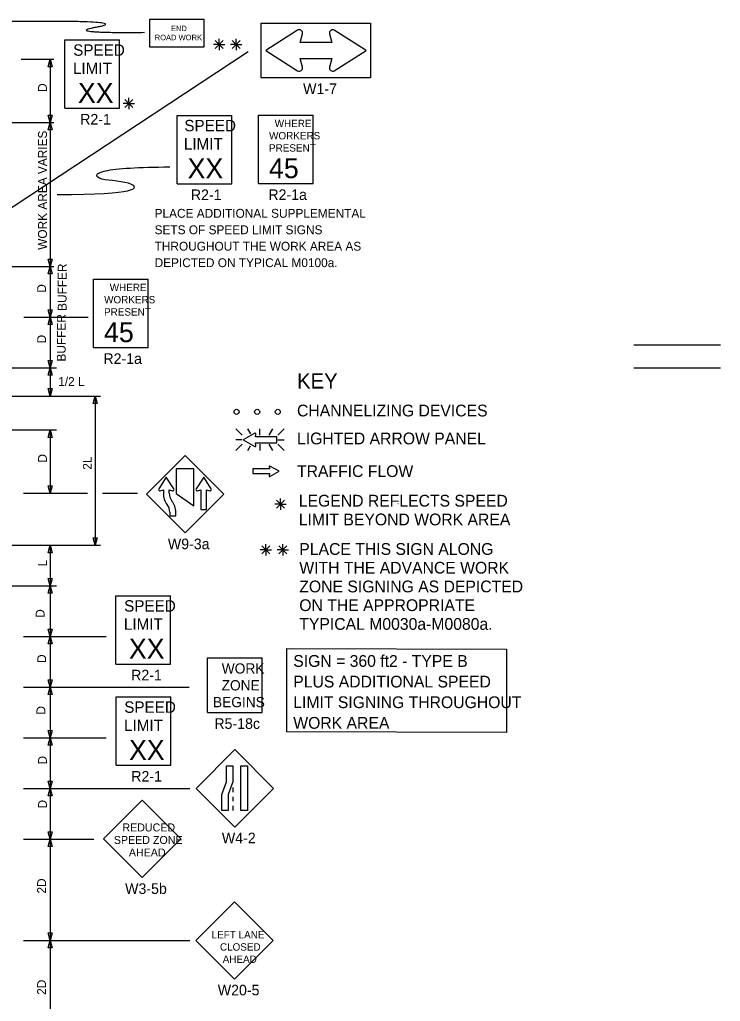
# Model space of a CAD drawing. Extents: x 16730 to 18482, y 5650 to 6977.
# Drawn here: x 17028 to 17582, y 6143 to 6919 of the extents above; entities that cross this region are included whole.
import ezdxf

# ---------------------------------------------------------------- set-up
doc = ezdxf.new("R2010")
doc.units = 0
for name, color, linetype in [('MT_SCRATCH_LEVEL_E', 7, 'Continuous'), ('TRAFFIC_SIGNS_PR', 7, 'Continuous'), ('TYPICAL_TEXT_DIMEN_EX', 7, 'Continuous'), ('TYPICAL_TEXT_DIMEN_PR', 7, 'Continuous')]:
    doc.layers.add(name, color=color, linetype=linetype)

msp = doc.modelspace()

# ---------------------------------------------------------------- linework, layer by layer
at = {"layer": 'MT_SCRATCH_LEVEL_E'}
for p, q in [((17225.23, 6563.7), (17211.98, 6563.7)), ((17211.98, 6563.7), (17211.98, 6559.96)), ((17224.92, 6565.48), (17225.23, 6563.7)), ((17232.84, 6561.85), (17225.6, 6565.96)), ((17225.6, 6557.7), (17232.84, 6561.85)), ((17211.98, 6559.96), (17225.23, 6559.96)), ((17225.23, 6559.96), (17224.92, 6558.18))]:
    msp.add_line(p, q, dxfattribs=at)
for centre, start, end in [((17225.38, 6565.55), 60.42484, 189.96381), ((17225.38, 6558.11), 170.03619, 299.77312)]:
    msp.add_arc(centre, 0.463, start, end, dxfattribs=at)
at = {"layer": 'TRAFFIC_SIGNS_PR'}
for p, q in [((17063.61, 6902.55), (17106.81, 6902.55)), ((17063.61, 6848.55), (17063.61, 6902.55)), ((17106.81, 6848.55), (17106.81, 6902.55)), ((17063.61, 6848.55), (17106.81, 6848.55)), ((17152.3, 6842.88), (17195.5, 6842.88)), ((17152.3, 6788.88), (17152.3, 6842.88)), ((17195.5, 6788.88), (17195.5, 6842.88)), ((17216.65, 6842.98), (17259.85, 6842.98)), ((17216.65, 6788.98), (17216.65, 6842.98)), ((17259.85, 6788.98), (17259.85, 6842.98)), ((17152.3, 6788.88), (17195.5, 6788.88)), ((17216.65, 6788.98), (17259.85, 6788.98)), ((17086.26, 6713.46), (17129.46, 6713.46)), ((17086.26, 6659.46), (17086.26, 6713.46)), ((17129.46, 6659.46), (17129.46, 6713.46)), ((17086.26, 6659.46), (17129.46, 6659.46)), ((17198.66, 6595.23), (17203.59, 6590.3)), ((17210.42, 6591.41), (17208.21, 6595.23)), ((17217.74, 6590.3), (17217.74, 6595.23)), ((17224.97, 6590.3), (17227.82, 6595.23)), ((17231.89, 6590.3), (17236.82, 6595.23)), ((17203.59, 6586.74), (17198.66, 6586.74)), ((17231.89, 6586.74), (17236.82, 6586.74)), ((17198.66, 6578.25), (17203.59, 6583.19)), ((17208.17, 6578.25), (17210.28, 6581.91)), ((17217.74, 6583.19), (17217.74, 6578.25)), ((17227.87, 6578.25), (17225.02, 6583.19)), ((17231.89, 6583.19), (17236.82, 6578.25)), ((17158.5, 6574.22), (17127.95, 6543.68)), ((17189.05, 6543.68), (17158.5, 6574.22)), ((17127.95, 6543.68), (17158.5, 6513.13)), ((17158.5, 6513.13), (17189.05, 6543.68)), ((17103.88, 6463.52), (17147.08, 6463.52)), ((17103.88, 6409.52), (17103.88, 6463.52)), ((17147.08, 6409.52), (17147.08, 6463.52)), ((17176.27, 6371.21), (17176.27, 6414.41)), ((17176.27, 6414.41), (17219.47, 6414.41)), ((17219.47, 6371.21), (17219.47, 6414.41)), ((17103.88, 6409.52), (17147.08, 6409.52)), ((17103.98, 6383.56), (17147.18, 6383.56)), ((17103.98, 6329.56), (17103.98, 6383.56)), ((17147.18, 6329.56), (17147.18, 6383.56)), ((17176.27, 6371.21), (17219.47, 6371.21)), ((17197.78, 6341.93), (17167.23, 6311.38)), ((17228.33, 6311.38), (17197.78, 6341.93)), ((17103.98, 6329.56), (17147.18, 6329.56)), ((17196.38, 6311.93), (17196.38, 6308.33)), ((17167.23, 6311.38), (17197.78, 6280.83)), ((17196.38, 6304.73), (17196.38, 6301.13)), ((17197.78, 6280.83), (17228.33, 6311.38)), ((17124.69, 6301.94), (17094.14, 6271.39)), ((17155.23, 6271.39), (17124.69, 6301.94)), ((17196.38, 6297.53), (17196.38, 6293.93)), ((17094.14, 6271.39), (17124.69, 6240.84)), ((17124.69, 6240.84), (17155.23, 6271.39)), ((17197.68, 6221.83), (17167.13, 6191.28)), ((17228.22, 6191.28), (17197.68, 6221.83)), ((17167.13, 6191.28), (17197.68, 6160.73)), ((17197.68, 6160.73), (17228.22, 6191.28))]:
    msp.add_line(p, q, dxfattribs=at)
for points in [[(17130.49, 6896.94), (17173.69, 6896.94), (17173.69, 6918.54), (17130.49, 6918.54)], [(17305.2, 6872.6), (17218.8, 6872.6), (17218.8, 6915.8), (17305.2, 6915.8)], [(17151.4, 6563.85), (17151.4, 6544.33), (17165.36, 6534.64), (17165.36, 6563.85)], [(17196.38, 6329.08), (17196.38, 6316.5), (17192.62, 6306.51), (17192.62, 6293.93), (17187.56, 6293.93), (17187.56, 6306.51), (17191.32, 6316.5), (17191.32, 6329.08)], [(17207.78, 6329.08), (17207.78, 6293.93), (17202.73, 6293.93), (17202.73, 6329.08)]]:
    msp.add_lwpolyline(points, close=True, dxfattribs=at)
for points in [[(17247.51, 6910.18), (17222.4, 6894.2), (17247.51, 6878.22)], [(17276.49, 6878.22), (17301.6, 6894.2), (17276.49, 6910.18)], [(17272.71, 6907.39), (17274.6, 6900.5), (17249.41, 6900.5), (17251.29, 6907.39)], [(17251.29, 6881.01), (17249.41, 6887.9), (17274.6, 6887.9), (17272.71, 6881.01)], [(17213.67, 6592.02), (17204.37, 6586.74), (17213.67, 6581.42)], [(17214.54, 6582.05), (17214.14, 6584.32), (17231.15, 6584.32), (17231.15, 6589.12), (17214.14, 6589.12), (17214.54, 6591.4)], [(17149.72, 6547.84), (17143.72, 6557.26), (17137.73, 6547.84)], [(17179.22, 6547.84), (17173.23, 6557.26), (17167.24, 6547.84)], [(17138.78, 6546.42), (17141.36, 6547.13), (17141.36, 6544.62)], [(17146.08, 6544.51), (17146.08, 6547.13), (17148.67, 6546.42)], [(17168.29, 6546.42), (17170.87, 6547.13), (17170.87, 6531.61), (17175.59, 6531.61), (17175.59, 6547.13), (17178.18, 6546.42)], [(17146.5, 6529.49), (17146.49, 6526.51), (17151.22, 6526.51), (17151.22, 6529.49)]]:
    msp.add_lwpolyline(points, dxfattribs=at)
for centre in [(17199.22, 6608.78), (17215.52, 6608.78), (17231.82, 6608.78)]:
    msp.add_circle(centre, 2, dxfattribs=at)
for centre, radius, start, end in [((17248.86, 6908.05), 2.52, 344.67308, 122.46963), ((17275.14, 6908.05), 2.52, 57.53038, 195.32692), ((17248.86, 6880.35), 2.52, 237.53038, 15.32692), ((17275.14, 6880.35), 2.52, 164.69282, 302.45235), ((17213.95, 6591.5), 0.598, 350.73078, 118.89165), ((17213.95, 6581.95), 0.597, 241.48329, 9.95933), ((17138.53, 6547.33), 0.945, 147.52044, 285.3986), ((17155.52, 6544.21), 14.17, 178.32933, 218.54273), ((17155.52, 6544.21), 9.45, 178.19356, 218.54646), ((17134.27, 6544.88), 11.81, 358.18937, 0.00483), ((17148.92, 6547.34), 0.947, 254.68281, 32.2708), ((17145.55, 6535.03), 11.81, 74.67996, 74.68078), ((17159.68, 6554.18), 11.81, 212.45689, 212.46649), ((17168.04, 6547.33), 0.946, 147.54971, 285.33159), ((17178.43, 6547.33), 0.943, 254.67777, 32.46648), ((17189.19, 6554.18), 11.81, 212.45689, 212.46649), ((17137.04, 6529.49), 14.17, 0, 38.5422), ((17137.04, 6529.49), 9.45, 0, 38.54567)]:
    msp.add_arc(centre, radius, start, end, dxfattribs=at)
msp.add_open_spline([(17126.47, 6908.26), (17060.05, 6907.48), (17118.8, 6918.29), (17010.82, 6916.87)], degree=2, dxfattribs=at)
at = {"layer": 'TYPICAL_TEXT_DIMEN_EX'}
msp.add_lwpolyline([(17238.99, 6421.71), (17412.66, 6421.33), (17412.66, 6355.56), (17238.99, 6355.94)], close=True, dxfattribs=at)
at = {"layer": 'TYPICAL_TEXT_DIMEN_PR'}
for p, q in [((17182.27, 6902.13), (17188.64, 6895.75)), ((17188.64, 6902.13), (17182.27, 6895.75)), ((17185.45, 6898.94), (17185.45, 6903.39)), ((17195.77, 6902.13), (17202.15, 6895.75)), ((17202.15, 6902.13), (17195.77, 6895.75)), ((17198.96, 6898.94), (17198.96, 6903.39)), ((17185.45, 6898.94), (17180.92, 6898.94)), ((17185.45, 6898.94), (17188.64, 6898.94)), ((17185.45, 6898.94), (17189.93, 6898.94)), ((17185.45, 6898.94), (17185.45, 6894.44)), ((17198.96, 6898.94), (17194.43, 6898.94)), ((17198.96, 6898.94), (17202.15, 6898.94)), ((17198.96, 6898.94), (17203.44, 6898.94)), ((17198.96, 6898.94), (17198.96, 6894.44)), ((17208.35, 6893.17), (16957.07, 6727.68)), ((17028.89, 6887.23), (17054.89, 6887.23)), ((17050.31, 6881.37), (17051.88, 6887.23)), ((17051.88, 6887.23), (17051.88, 6837.23)), ((17051.88, 6887.23), (17053.45, 6881.37)), ((17051.88, 6881.37), (17050.31, 6881.37)), ((17053.45, 6881.37), (17051.88, 6881.37)), ((17117.25, 6855.5), (17110.87, 6849.12)), ((17110.88, 6855.5), (17117.25, 6849.12)), ((17114.06, 6852.31), (17114.06, 6856.76)), ((17114.06, 6852.31), (17109.53, 6852.31)), ((17114.06, 6852.31), (17117.25, 6852.31)), ((17114.06, 6852.31), (17118.54, 6852.31)), ((17114.06, 6852.31), (17114.06, 6847.81)), ((17051.88, 6837.23), (17050.31, 6843.09)), ((17050.31, 6843.09), (17051.88, 6843.09)), ((17051.88, 6843.09), (17053.45, 6843.09)), ((17053.45, 6843.09), (17051.88, 6837.23)), ((16968.82, 6837.23), (17054.89, 6837.23)), ((17050.31, 6831.37), (17051.88, 6837.23)), ((17051.88, 6837.23), (17051.88, 6723.51)), ((17051.88, 6837.23), (17053.45, 6831.37)), ((17051.88, 6831.37), (17050.31, 6831.37)), ((17053.45, 6831.37), (17051.88, 6831.37)), ((16965.89, 6723.51), (17054.89, 6723.51)), ((17051.88, 6723.51), (17050.31, 6729.37)), ((17050.31, 6729.37), (17051.88, 6729.37)), ((17050.31, 6717.64), (17051.88, 6723.51)), ((17051.88, 6729.37), (17053.45, 6729.37)), ((17053.45, 6729.37), (17051.88, 6723.51)), ((17051.88, 6723.51), (17051.88, 6683.51)), ((17051.88, 6723.51), (17053.45, 6717.64)), ((17051.88, 6717.64), (17050.31, 6717.64)), ((17053.45, 6717.64), (17051.88, 6717.64)), ((17051.88, 6683.51), (17050.31, 6689.37)), ((17050.31, 6689.37), (17051.88, 6689.37)), ((17051.88, 6690.6), (17051.88, 6687.01)), ((17051.88, 6689.37), (17053.45, 6689.37)), ((17053.45, 6689.37), (17051.88, 6683.51)), ((17031.1, 6683.51), (17081.87, 6683.51)), ((17050.31, 6677.64), (17051.88, 6683.51)), ((17051.88, 6677.64), (17050.31, 6677.64)), ((17051.88, 6683.51), (17051.88, 6643.51)), ((17051.88, 6683.51), (17053.45, 6677.64)), ((17053.45, 6677.64), (17051.88, 6677.64)), ((17513.29, 6661.57), (17581.65, 6661.57)), ((17051.88, 6643.51), (17050.31, 6649.37)), ((17050.31, 6649.37), (17051.88, 6649.37)), ((17051.88, 6650.6), (17051.88, 6647.01)), ((17051.88, 6649.37), (17053.45, 6649.37)), ((17053.45, 6649.37), (17051.88, 6643.51)), ((16967.88, 6643.51), (17056.88, 6643.51)), ((17050.31, 6637.64), (17051.88, 6643.51)), ((17051.88, 6637.64), (17050.31, 6637.64)), ((17051.88, 6643.51), (17051.88, 6621.26)), ((17051.88, 6643.51), (17053.45, 6637.64)), ((17053.45, 6637.64), (17051.88, 6637.64)), ((17513.29, 6643.51), (17581.65, 6643.51)), ((17051.88, 6621.26), (17050.31, 6627.12)), ((17050.31, 6627.12), (17051.88, 6627.12)), ((17051.88, 6627.12), (17053.45, 6627.12)), ((17053.45, 6627.12), (17051.88, 6621.26)), ((16970.81, 6621.26), (17091.69, 6621.26)), ((17085.79, 6615.4), (17087.36, 6621.26)), ((17087.36, 6615.4), (17085.79, 6615.4)), ((17087.36, 6621.26), (17087.36, 6503.38)), ((17087.36, 6621.26), (17088.93, 6615.4)), ((17088.93, 6615.4), (17087.36, 6615.4)), ((16957.13, 6594.45), (17056.88, 6594.45)), ((17050.31, 6588.59), (17051.88, 6594.45)), ((17051.88, 6594.45), (17051.88, 6544.45)), ((17051.88, 6594.45), (17053.45, 6588.59)), ((17051.88, 6588.59), (17050.31, 6588.59)), ((17053.45, 6588.59), (17051.88, 6588.59)), ((17051.88, 6544.45), (17050.31, 6550.32)), ((17050.31, 6550.32), (17051.88, 6550.32)), ((17051.88, 6550.32), (17053.45, 6550.32)), ((17053.45, 6550.32), (17051.88, 6544.45)), ((17030.88, 6544.45), (17081.5, 6544.45)), ((17093.22, 6544.45), (17121.03, 6544.45)), ((17237.07, 6538.99), (17230.69, 6532.62)), ((17230.7, 6538.99), (17237.07, 6532.62)), ((17233.88, 6535.81), (17233.88, 6540.26)), ((17233.88, 6535.81), (17229.35, 6535.81)), ((17233.88, 6535.81), (17237.07, 6535.81)), ((17233.88, 6535.81), (17238.36, 6535.81)), ((17233.88, 6535.81), (17233.88, 6531.31)), ((17087.36, 6503.38), (17085.79, 6509.25)), ((17085.79, 6509.25), (17087.36, 6509.25)), ((17087.36, 6509.25), (17088.93, 6509.25)), ((17088.93, 6509.25), (17087.36, 6503.38)), ((16947.63, 6503.38), (17091.69, 6503.38)), ((17050.31, 6497.52), (17051.88, 6503.38)), ((17051.88, 6503.38), (17051.88, 6471.28)), ((17051.88, 6503.38), (17053.45, 6497.52)), ((17222.38, 6499.69), (17217.84, 6499.69)), ((17219.19, 6502.88), (17225.56, 6496.5)), ((17225.56, 6502.88), (17219.19, 6496.5)), ((17222.38, 6499.69), (17222.38, 6504.14)), ((17222.38, 6499.69), (17225.56, 6499.69)), ((17222.38, 6499.69), (17226.85, 6499.69)), ((17222.38, 6499.69), (17222.38, 6495.19)), ((17235.88, 6499.69), (17231.35, 6499.69)), ((17239.07, 6502.88), (17232.69, 6496.5)), ((17232.7, 6502.88), (17239.07, 6496.5)), ((17235.88, 6499.69), (17235.88, 6504.14)), ((17235.88, 6499.69), (17239.07, 6499.69)), ((17235.88, 6499.69), (17240.36, 6499.69)), ((17235.88, 6499.69), (17235.88, 6495.19)), ((17051.88, 6497.52), (17050.31, 6497.52)), ((17053.45, 6497.52), (17051.88, 6497.52)), ((17051.88, 6471.28), (17050.31, 6477.14)), ((17050.31, 6477.14), (17051.88, 6477.14)), ((17051.88, 6477.14), (17053.45, 6477.14)), ((17053.45, 6477.14), (17051.88, 6471.28)), ((16928.28, 6471.28), (17056.88, 6471.28)), ((17050.31, 6465.42), (17051.88, 6471.28)), ((17051.88, 6471.28), (17051.88, 6421.28)), ((17051.88, 6471.28), (17053.45, 6465.42)), ((17051.88, 6465.42), (17050.31, 6465.42)), ((17053.45, 6465.42), (17051.88, 6465.42)), ((17051.88, 6431.28), (17050.31, 6437.14)), ((17050.31, 6437.14), (17051.88, 6437.14)), ((17051.88, 6437.14), (17053.45, 6437.14)), ((17053.45, 6437.14), (17051.88, 6431.28)), ((17030.88, 6431.28), (17096.13, 6431.28)), ((17050.31, 6425.42), (17051.88, 6431.28)), ((17051.88, 6431.28), (17051.88, 6391.28)), ((17051.88, 6431.28), (17053.45, 6425.42)), ((17051.88, 6425.42), (17050.31, 6425.42)), ((17053.45, 6425.42), (17051.88, 6425.42)), ((17030.88, 6391.28), (17161.73, 6391.28)), ((17051.88, 6391.28), (17050.31, 6397.14)), ((17050.31, 6397.14), (17051.88, 6397.14)), ((17050.31, 6385.42), (17051.88, 6391.28)), ((17051.88, 6397.14), (17053.45, 6397.14)), ((17053.45, 6397.14), (17051.88, 6391.28)), ((17051.88, 6391.28), (17053.45, 6385.42)), ((17051.88, 6391.28), (17051.88, 6351.28)), ((17051.88, 6385.42), (17050.31, 6385.42)), ((17053.45, 6385.42), (17051.88, 6385.42)), ((17030.88, 6351.28), (17096.13, 6351.28)), ((17051.88, 6351.28), (17050.31, 6357.14)), ((17050.31, 6357.14), (17051.88, 6357.14)), ((17050.31, 6345.42), (17051.88, 6351.28)), ((17051.88, 6357.14), (17053.45, 6357.14)), ((17053.45, 6357.14), (17051.88, 6351.28)), ((17051.88, 6351.28), (17053.45, 6345.42)), ((17051.88, 6351.28), (17051.88, 6311.28)), ((17051.88, 6345.42), (17050.31, 6345.42)), ((17053.45, 6345.42), (17051.88, 6345.42)), ((17051.88, 6311.28), (17050.31, 6317.14)), ((17050.31, 6317.14), (17051.88, 6317.14)), ((17051.88, 6317.14), (17053.45, 6317.14)), ((17053.45, 6317.14), (17051.88, 6311.28)), ((17030.88, 6311.28), (17162.32, 6311.28)), ((17050.31, 6305.42), (17051.88, 6311.28)), ((17051.88, 6305.42), (17050.31, 6305.42)), ((17051.88, 6311.28), (17051.88, 6271.28)), ((17051.88, 6311.28), (17053.45, 6305.42)), ((17053.45, 6305.42), (17051.88, 6305.42)), ((17051.88, 6271.28), (17050.31, 6277.14)), ((17050.31, 6277.14), (17051.88, 6277.14)), ((17051.88, 6277.14), (17053.45, 6277.14)), ((17053.45, 6277.14), (17051.88, 6271.28)), ((17030.88, 6271.28), (17086.42, 6271.28)), ((17050.31, 6265.42), (17051.88, 6271.28)), ((17051.88, 6265.42), (17050.31, 6265.42)), ((17051.88, 6271.28), (17053.45, 6265.42)), ((17051.88, 6271.28), (17051.88, 6191.28)), ((17053.45, 6265.42), (17051.88, 6265.42)), ((17051.88, 6191.28), (17050.31, 6197.14)), ((17050.31, 6197.14), (17051.88, 6197.14)), ((17051.88, 6197.14), (17053.45, 6197.14)), ((17053.45, 6197.14), (17051.88, 6191.28)), ((17030.88, 6191.28), (17162.3, 6191.28)), ((17050.31, 6185.42), (17051.88, 6191.28)), ((17051.88, 6191.28), (17053.45, 6185.42)), ((17051.88, 6191.28), (17051.88, 6111.28)), ((17051.88, 6185.42), (17050.31, 6185.42)), ((17053.45, 6185.42), (17051.88, 6185.42))]:
    msp.add_line(p, q, dxfattribs=at)
for points, degree in [([(17057.36, 6780.37), (17121.94, 6780.37), (17121.94, 6791.12), (17087.02, 6791.12), (17087.02, 6800.21), (17121.72, 6801.96), (17146.39, 6802.25)], 3), ([(17256.2, 6599.57), (17256.21, 6599.57), (17256.22, 6599.57), (17256.22, 6599.57)], 2), ([(17326.83, 6536.39), (17326.85, 6536.39), (17326.86, 6536.39), (17326.86, 6536.39)], 2)]:
    msp.add_open_spline(points, degree=degree, dxfattribs=at)

# ---------------------------------------------------------------- texts
at = {"layer": 'TRAFFIC_SIGNS_PR'}
for s, height, p in [('END', 4.31, (17147.37, 6909.46)), ('ROAD WORK', 4.31, (17134.55, 6902.28)), ('SPEED', 9, (17070.09, 6890.02)), ('LIMIT', 9, (17069.91, 6875.62)), ('XX', 15.785, (17073.86, 6852.78)), ('W1-7', 8.37, (17251.83, 6859.73)), ('R2-1', 8.37, (17075.62, 6835.68)), ('SPEED', 9, (17157.96, 6830.35)), ('WHERE', 5.85, (17229.37, 6833.62)), ('LIMIT', 9, (17157.59, 6815.95)), ('WORKERS', 5.85, (17224.95, 6823.95)), ('PRESENT', 5.85, (17224.88, 6814.27)), ('XX', 15.785, (17160.52, 6793.11)), ('45', 15.785, (17224.87, 6793.31)), ('R2-1', 8.37, (17163.11, 6776.01)), ('R2-1a', 8.37, (17224.36, 6776.11)), ('PLACE ADDITIONAL SUPPLEMENTAL', 7, (17134.46, 6762.05)), ('SETS OF SPEED LIMIT SIGNS', 7, (17134.46, 6749.05)), ('THROUGHOUT THE WORK AREA AS', 7, (17134.46, 6736.05)), ('DEPICTED ON TYPICAL M0100a.', 7, (17134.46, 6723.05)), ('WHERE', 5.85, (17098.98, 6704.1)), ('WORKERS', 5.85, (17094.56, 6694.43)), ('PRESENT', 5.85, (17094.49, 6684.75)), ('45', 15.785, (17094.48, 6663.79)), ('R2-1a', 8.37, (17093.97, 6646.59)), ('W9-3a', 8.37, (17144.93, 6500.26)), ('PLACE THIS SIGN ALONG', 9.3, (17248.82, 6495.78)), ('WITH THE ADVANCE WORK', 9.3, (17248.82, 6480.98)), ('ZONE SIGNING AS DEPICTED', 9.3, (17248.82, 6466.18)), ('SPEED', 9, (17110.37, 6450.99)), ('ON THE APPROPRIATE', 9.3, (17248.82, 6451.38)), ('LIMIT', 9, (17110.19, 6436.59)), ('TYPICAL M0030a-M0080a.', 9.3, (17248.82, 6436.58)), ('XX', 15.785, (17114.14, 6413.75)), ('R2-1', 8.37, (17115.89, 6396.66)), ('WORK', 8.119, (17187.52, 6402)), ('ZONE', 8.119, (17187.39, 6388.71)), ('BEGINS', 8.119, (17180.56, 6375.43)), ('SPEED', 9, (17110.47, 6371.03)), ('R5-18c', 8.37, (17181.68, 6358.34)), ('LIMIT', 9, (17110.28, 6356.63)), ('XX', 15.785, (17114.23, 6333.79)), ('R2-1', 8.37, (17115.99, 6316.69)), ('REDUCED', 6.3, (17109, 6277.36)), ('SPEED ZONE', 6.3, (17102.24, 6267.46)), ('W4-2', 8.37, (17187.61, 6267.96)), ('AHEAD', 6.3, (17114.12, 6257.56)), ('W3-5b', 8.37, (17111.13, 6227.97)), ('LEFT LANE', 5.85, (17179.54, 6192.85)), ('CLOSED', 5.85, (17186.11, 6183.18)), ('AHEAD', 5.85, (17188.29, 6173.5)), ('W20-5', 8.37, (17184.37, 6147.87))]:
    msp.add_text(s, height=height, dxfattribs=at).set_placement(p)
at = {"layer": 'TYPICAL_TEXT_DIMEN_EX'}
for s, height, p in [('KEY', 12, (17247.01, 6627.18)), ('CHANNELIZING DEVICES', 9.3, (17247.01, 6605.13)), ('LIGHTED ARROW PANEL', 9.3, (17247.01, 6583.08)), ('TRAFFIC FLOW', 9.3, (17247.01, 6557.28)), ('LEGEND REFLECTS SPEED', 9.3, (17248.43, 6533.91)), ('LIMIT BEYOND WORK AREA', 9.3, (17248.43, 6519.11)), ('SIGN = 360 ft2 - TYPE B', 9.3, (17244.04, 6407.34)), ('PLUS ADDITIONAL SPEED', 9.3, (17244.04, 6391.04)), ('LIMIT SIGNING THROUGHOUT', 9.3, (17244.04, 6374.74)), ('WORK AREA', 9.3, (17244.04, 6358.44))]:
    msp.add_text(s, height=height, dxfattribs=at).set_placement(p)
at = {"layer": 'TYPICAL_TEXT_DIMEN_PR'}
for s, p in [('D', (17049.32, 6861.45)), ('WORK AREA VARIES', (17049.32, 6736.73)), ('BUFFER', (17064.91, 6688.47)), ('D', (17048.64, 6702.83)), ('BUFFER', (17064.19, 6648.47)), ('D', (17048.64, 6662.83)), ('D', (17049.32, 6568.67)), ('2L', (17084.8, 6563.04)), ('L', (17049.32, 6486.69)), ('D', (17047.47, 6446.11)), ('D', (17048.7, 6410.42)), ('D', (17048.09, 6369.64)), ('D', (17049.32, 6330.24)), ('D', (17049.32, 6295.5)), ('2D', (17048.6, 6228.27)), ('2D', (17048.6, 6148.27))]:
    msp.add_text(s, height=7, rotation=90, dxfattribs=at).set_placement(p)
msp.add_text('1/2 L', height=7, dxfattribs=at).set_placement((17058.28, 6629.18))

doc.saveas('drawing.dxf')
